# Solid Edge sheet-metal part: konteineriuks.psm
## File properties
Author: Indrek
Template: Normal.psm
Last saved by: Indrek
Revision: 3
Application: Solid Edge
Accuracy: 0,990
Material Thickness: 1,00 mm
Bend Radius: 1,00 mm
Relief Width: 1,00 mm
Relief Length: 0,00 mm
Neutral Factor: 0,330
Minimum Arc Length: 0,10 mm
Deviational Tolerance: 0,10 mm
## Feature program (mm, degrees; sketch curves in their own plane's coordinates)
base tab "unnamed BaseTab 1"
flange "Flange_1"
dimple "Dimple_3"
louver "Louver_5"  LouverDepth = 2.641 mm; LouverHeight = 1.5345 mm
bead "unnamed Bead 1"
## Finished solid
Body 1: solid body, 54 faces, 126 edges, 78 vertices.
  Faces by surface: plane 26, cylinder 16, cone 4, sphere 4, torus 4
  Edges by curve: line 80, circle 38, ellipse 8
Bounding box of the edges (mm; curved faces can reach further): 21.443 x 48.000 x 27.000, from (-19.193, -39.0378, 18.7721) to (2.25, 8.9622, 45.7721).
Cylindrical faces by radius (mm): R1 x13, R2 x1, R2.0401 x1, R3.0401 x1
Conical faces (half-angle, radius in mm at the cone's reference point): 15 deg R0.3014 x1, 15 deg R0.6363 x1, 15 deg R1.2673 x1, 15 deg R1.6023 x1
Toroidal faces (ring radius, tube radius in mm): R0.5 r1 x2, R1.6023 r1 x2
Spherical faces by radius (mm): R2.0401 x2, R3.0401 x2
Planar faces by outward normal: +x 3, +y 3, +z 4, -x 4, -y 3, -z 5, oblique 4
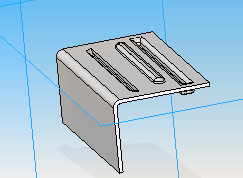
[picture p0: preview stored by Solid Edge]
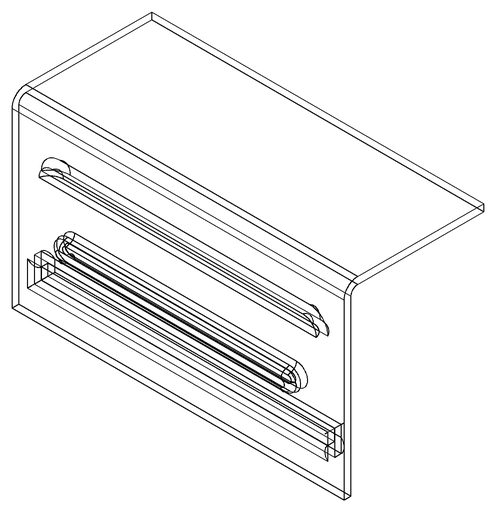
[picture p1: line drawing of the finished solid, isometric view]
